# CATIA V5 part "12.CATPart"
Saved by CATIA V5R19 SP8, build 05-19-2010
Part number: 1
Bounding box of the stored display mesh (mm): x -230 to 10, y -16 to 6, z -24.997 to 24.997
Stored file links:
  U:\IAOm\12.CATPart
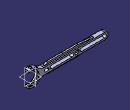
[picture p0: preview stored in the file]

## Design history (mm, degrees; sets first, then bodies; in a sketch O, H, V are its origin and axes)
Parameters
  AE1 = 180 mm
  AD1 = 70 mm
Body1 (main body)
  Sketch1 on zx-plane, origin (0, 0, 0), H (-1, 0, 0), V (0, 0, 1)
    line L1 (35.7071, -10) -> (220, -10)
    line L2 (220, 10) -> (35.7071, 10)
    point P1 (220, -10)
    point P2 (220, 10)
    construction line L3 (150, 0) -> (220, 0)
    point P3 (150, 0)
    line L4 (150, 5) -> (220, 5)
    line L5 (220, -5) -> (150, -5)
    arc A1 centre (220, 0) radius 5 from (220, 5) to (220, -5) cw
    arc A2 centre (150, 0) radius 5 from (150, -5) to (150, 5) cw
    construction line L6 (60, 0) -> (120, 0)
    point P9 (60, 0)
    point P10 (120, 0)
    line L7 (60, 5) -> (120, 5)
    line L8 (120, -5) -> (60, -5)
    arc A3 centre (120, 0) radius 5 from (120, 5) to (120, -5) cw
    arc A4 centre (60, 0) radius 5 from (60, -5) to (60, 5) cw
    arc A5 centre (0, 0) radius 20 from (-10, 17.3205) to (-10, -17.3205) cw
    point P15 (0, 0)
    line L9 (-10, 17.3205) -> (-10, 22.9129)
    point P18 (-10, 22.9129)
    line L10 (-10, -17.3205) -> (-10, -22.9129)
    arc A6 centre (0, 0) radius 25 from (-10, 22.9129) to (17.8536, 17.5) cw
    point P20 (0, 0)
    point P21 (-10, 22.9129)
    point P22 (22.9129, -10)
    arc A7 centre (0, 0) radius 25 from (17.8536, -17.5) to (-10, -22.9129) cw
    construction line L11 (20, 36.6166) -> (20, -39.7535)
    arc A8 centre (220, 0) radius 10 from (220, 10) to (220, -10) cw
    point P25 (220, 0)
    axis line L12 (-10, 39.084) -> (-10, -27.4612)
    reference projected point E1 (0, 0) from Sketch6
    arc A9 centre (35.7071, 35) radius 25 from (17.8536, 17.5) to (35.7071, 10) ccw
    arc A10 centre (35.7071, -35) radius 25 from (17.8536, -17.5) to (35.7071, -10) cw
    distance L3 L4 = 5
    distance L3 L1 = 10
    length L5 = 70
    distance L6 L7 = 5
    length L7 = 60
    distance P10 P3 = 30
    distance L11 A5 = 0
    radius A5 = 20
    distance P1 P2 = 20
    distance A1 A8 = 5
    distance L12 V = 10
    distance L9 P25 = 230
    radius A6 = 25
    radius A9 = 25
    radius A10 = 25
    horizontal: L1 H, L2 H, L3 H, L6 H
    tangency: A1 L4, A2 L4, A1 L5, A2 L5, A3 L7, A4 L7, A3 L8, A4 L8, A8 L1, A8 L2, A9 A6, A9 L2, A10 A7, A10 L1
    coincidence: P9 L3, P15 L6, P21 P18, P20 P15, A6 P22, A6 A7, L6 H, L9 L12, L10 L9, A7 P22, L1 P22
    vertical: L9 V, L10 V, L11 V, L12 V
    concentricity: A5 E1
  Pad1: profile Sketch1, direction (0, 1, 0), length 6, mirrored extent
  Sketch2 on xy-plane, origin (0, 0, 0), H (1, 0, 0), V (0, 1, 0)
    circle A1 centre (0, 0) radius 4
    point P1 (0, 0)
    radius A1 = 4
    coincidence: P1 O
  Pocket1: profile Sketch2, direction (0, 0, -1), through (limit type 3), opposite side through (limit type 3)
  Sketch3 on start face of Pad1, origin (0, -6, 0), H (1, 0, 0), V (0, 0, 1)
    circle A1 centre (-29, 0) radius 4
    point P1 (-29, 0)
    reference projected arc E1 centre (0, 0) radius 20 from (10, 17.3205) to (10, -17.3205) ccw from edge [start face of Pad1 | face of Pad1 from Sketch1.A5]
    radius A1 = 4
    distance A1 E1 = 5
    coincidence: P1 H
  Pad2: profile Sketch3, direction (0, -1, 0), length 10
  Sketch4 on zx-plane, origin (0, 0, 0), H (-1, 0, 0), V (0, 0, 1)
    arc A1 centre (0, 0) radius 15 from (6, -13.7477) to (6, 13.7477) ccw
    point P1 (6, -13.7477)
    point P2 (6, 13.7477)
    construction line L1 (6, 36.7811) -> (6, -37.0173)
    reference projected arc E1 centre (0, 0) radius 20 from (-10, -17.3205) to (-10, 17.3205) ccw from edge [face of Pad1 from Sketch1.A5 | end face of Pad1]
    arc A2 centre (0, 0) radius 20 from (6, -19.0788) to (6, 19.0788) ccw
    point P5 (6, 19.0788)
    point P6 (6, -19.0788)
    reference projected arc E2 centre (0, 0) radius 20 from (-10, -17.3205) to (-10, 17.3205) ccw from edge [face of Pad1 from Sketch1.A5 | end face of Pad1]
    line L2 (6, -19.0788) -> (6, -13.7477)
    line L3 (6, 13.7477) -> (6, 19.0788)
    construction line L4 (232.1602, 0) -> (-35.1645, 0)
    point P7 (232.1602, 0)
    point P9 (41, 10)
    line L5 (41, 10) -> (49.6603, 15)
    point P10 (49.6603, 15)
    line L6 (49.6603, 15) -> (96, 15)
    line L7 (96, 10) -> (41, 10)
    reference projected line E3 (220, 10) -> (35.7071, 10) from edge [face of Pad1 from Sketch1.L2 | end face of Pad1]
    point P11 (49.6603, 15)
    point P12 (49.6603, 15)
    axis line L8 (96, 56.5793) -> (96, -31.7607)
    point P15 (96, 15)
    point P16 (96, 10)
    point P17 (96, 15)
    point P18 (96, 10)
    point P19 (189.9116, 10)
    point P20 (142.3397, 15)
    point P21 (142.3397, 15)
    point P22 (142.3397, 15)
    point P23 (96, 15)
    point P24 (96, 10)
    point P25 (96, 15)
    point P26 (96, 10)
    line L9 (189.9116, 10) -> (142.3397, 15)
    line L10 (142.3397, 15) -> (96, 15)
    line L11 (96, 10) -> (189.9116, 10)
    point P27 (41, -10)
    point P28 (49.6603, -15)
    point P29 (49.6603, -15)
    point P30 (49.6603, -15)
    point P31 (96, -15)
    point P32 (96, -10)
    point P33 (96, -15)
    point P34 (96, -10)
    point P35 (189.9116, -10)
    point P36 (142.3397, -15)
    point P37 (142.3397, -15)
    point P38 (142.3397, -15)
    point P39 (96, -15)
    point P40 (96, -10)
    point P41 (96, -15)
    point P42 (96, -10)
    line L12 (41, -10) -> (49.6603, -15)
    line L13 (49.6603, -15) -> (96, -15)
    line L14 (96, -10) -> (41, -10)
    line L15 (189.9116, -10) -> (142.3397, -15)
    line L16 (142.3397, -15) -> (96, -15)
    line L17 (96, -10) -> (189.9116, -10)
    reference projected line E4 (220, 10) -> (35.7071, 10) from edge [face of Pad1 from Sketch1.L2 | end face of Pad1]
    distance L1 V = 6
    radius A1 = 15
    distance L6 L7 = 5
    angle L5 L7 = 30
    distance P9 L1 = 35
    distance L8 P9 = 55
    angle L11 L9 = 6
    vertical: L1 V, L2 V, L3 V, L8 V
    coincidence: L1 P2, P1 L1, P5 L1, P6 L1, A2 E2, P7 H, L7 E3, L6 P12, L5 P10, L8 P15, L8 P16, P11 P10, P16 P24, P15 P23, P20 P21, P28 P29, P31 P39, P32 P40, P36 P37, L11 E4
    concentricity: A1 E1
    horizontal: L6 H, L7 H
    symmetry: P10 P20 L8, P11 P21 L8, P15 P23 L8, P16 P24 L8, P9 P27 L4, P10 P28 L4, P11 P29 L4, P12 P30 L4, P15 P31 L4, P16 P32 L4, P17 P33 L4, P18 P34 L4, P19 P35 L4, P20 P36 L4, P21 P37 L4, P22 P38 L4, P23 P39 L4, P24 P40 L4, P25 P41 L4, P26 P42 L4, L5 L12 L4, L6 L13 L4, L7 L14 L4, L9 L15 L4, L10 L16 L4, L11 L17 L4
  Pad3: profile Sketch4, direction (0, 1, 0), length 2.5, mirrored extent
  Fillet1: radius 2, on edge [face of Pad3 from Sketch4.L3 | face of Pad1 from Sketch1.A5]
  Fillet2: radius 2, on edge [face of Pad1 from Sketch1.A5 | face of Pad3 from Sketch4.L2]
  Fillet3: radius 3, on edge [face of Pad1 from Sketch1.L2 | face of Pad3 from Sketch4.L5]; edge [face of Pad3 from Sketch4.L5 | face of Pad3 from Sketch4.L6]
  Fillet4: radius 3, on edge [face of Pad3 from Sketch4.L9 | face of Pad1 from Sketch1.L2]; edge [face of Pad3 from Sketch4.L10 | face of Pad3 from Sketch4.L9]; edge [face of Pad1 from Sketch1.L1 | face of Pad3 from Sketch4.L15]; edge [face of Pad3 from Sketch4.L15 | face of Pad3 from Sketch4.L16]; edge [face of Pad3 from Sketch4.L13 | face of Pad3 from Sketch4.L12]; edge [face of Pad3 from Sketch4.L12 | face of Pad1 from Sketch1.L1]
  Fillet5: radius 4, on edge [face of Pad3 from Sketch4.L2 | face of Pad3 from Sketch4.A1]; edge [face of Pad3 from Sketch4.A1 | face of Pad3 from Sketch4.L3]
  Sketch5 on end face of Pad1, origin (0, 6, 0), H (-1, 0, 0), V (0, 0, 1)
    construction line L1 (253.4328, 0) -> (-63.0915, 0)
    point P1 (253.4328, 0)
    spline S1 through (34.6596, 0) (40.1724, 4.1365) (52.8056, 0)
    point P3 (129, 5)
    line L2 (131, 5) -> (139, 5)
    line L3 (141, 3) -> (141, 0)
    line L4 (129, 0) -> (129, 3)
    point P4 (141, 5)
    point P5 (141, 0)
    point P6 (129, 0)
    reference projected line E1 (120, 5) -> (60, 5) from edge [end face of Pad1 | face of Pad1 from Sketch1.L7]
    spline S2 through (34.6596, 0) (40.1724, -4.1365) (52.8056, 0)
    point P7 (129, -5)
    point P8 (129, 0)
    line L5 (129, 0) -> (129, -3)
    point P9 (141, -5)
    line L6 (131, -5) -> (139, -5)
    point P10 (141, 0)
    line L7 (141, -3) -> (141, 0)
    axis line L8 (135, 24.944) -> (135, -24.0978)
    reference projected point E2 (150, 0) from axis of face of Pad1 from Sketch1.A2
    arc A1 centre (131, 3) radius 2 from (129, 3) to (131, 5) cw
    arc A2 centre (139, 3) radius 2 from (139, 5) to (141, 3) cw
    arc A3 centre (139, -3) radius 2 from (139, -5) to (141, -3) ccw
    arc A4 centre (131, -3) radius 2 from (131, -5) to (129, -3) cw
    arc A5 centre (48.1421, 0) radius 2.8131 from (49.6432, 2.3791) to (49.6432, -2.3791) cw
    arc A6 centre (39.9879, 0) radius 3.6605 from (38.002, 3.075) to (38.002, -3.075) ccw
    point P31 (34.6596, 0)
    point P32 (52.8056, 0)
    point P33 (52.8056, 0)
    point P34 (34.6596, 0)
    point P35 (40.1724, 4.1365)
    point P36 (40.1724, -4.1365)
    distance L2 E1 = 0
    distance L8 E2 = 15
    distance L3 L8 = 6
    distance L4 L8 = 6
    radius A1 = 2
    radius A2 = 2
    radius A3 = 2
    radius A4 = 2
    radius A5 = 2.8131
    radius A6 = 3.6605
    coincidence: P1 H, P31 L1, P32 L1, P5 L1, P31 P34, P32 P33, P5 P10, P6 P8, L4 P3, L2 P3, L2 P4, L3 P4, L6 P9, L7 P9, L6 P7, L5 P7
    horizontal: L1 H, L2 H
    vertical: L3 V, L4 V, L8 V
    symmetry: S1 S2 L1, P3 P7 L1, P6 P8 L1, L4 L5 L1, P4 P9 L1, L2 L6 L1, P5 P10 L1, L3 L7 L1, P32 P33 L1, P31 P34 L1, P35 P36 L1
    tangency: A1 L4, A1 L2, A2 L2, A2 L3, A3 L6, A3 L7, A4 L6, A4 L5, A5 S1, A5 S2, A6 S1, A6 S2
  Pocket2: profile Sketch5, direction (0, -1, 0), through (limit type 6)
  Sketch6, origin (7.4637, -11, -2.8797), H (-0.933, 0, 0.36), V (0.36, 0, 0.933), geometry linked from another document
